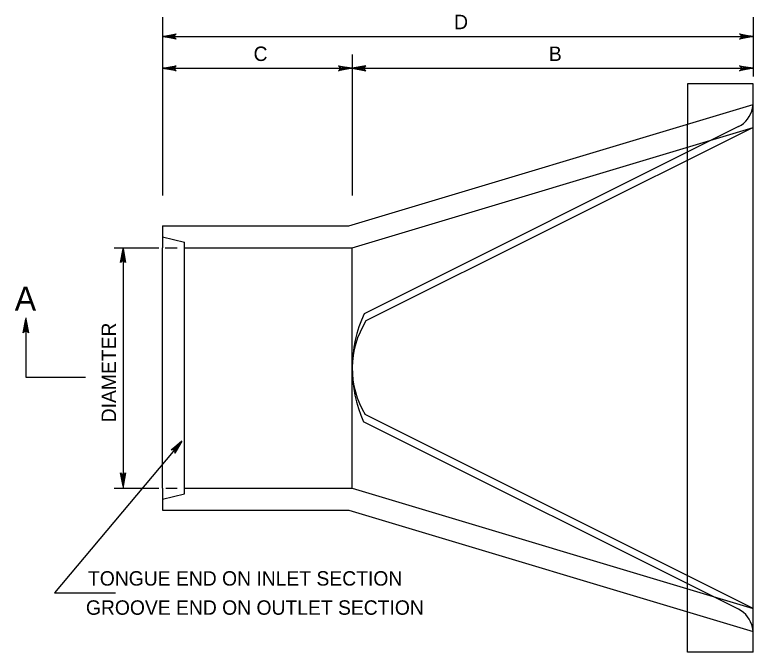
# Model space of a CAD drawing. Extents: x 1 to 8.2, y -2.1 to 8.1.
# Drawn here: x 0.968 to 4.037, y 5.467 to 8.117 of the extents above; entities that cross this region are included whole.
import ezdxf

# ---------------------------------------------------------------- set-up
doc = ezdxf.new("R2010")
doc.units = 0
for name, color, linetype in [('DETL-DIMS', 7, 'Continuous'), ('DETL-LINE', 7, 'Continuous'), ('DETL-NOTE', 7, 'Continuous'), ('DETL-TITL', 7, 'Continuous')]:
    doc.layers.add(name, color=color, linetype=linetype)

msp = doc.modelspace()

# ---------------------------------------------------------------- linework, layer by layer
at = {"layer": 'DETL-DIMS'}
for p, q in [((1.5824, 8.1071), (1.5824, 7.3661)), ((4.0369, 8.1071), (4.0369, 7.8601)), ((1.5824, 8.0267), (4.0369, 8.0267)), ((2.3702, 7.952), (2.3702, 7.3661)), ((1.5824, 7.8945), (2.3702, 7.8945)), ((2.3702, 7.8945), (4.0369, 7.8945)), ((1.3817, 7.1487), (1.5673, 7.1487)), ((1.4191, 7.1487), (1.4191, 6.1487)), ((1.5931, 7.1487), (1.6426, 7.1487)), ((1.0147, 6.6096), (1.0147, 6.8564)), ((1.2615, 6.6096), (1.0147, 6.6096)), ((1.6617, 6.345), (1.1335, 5.7132)), ((1.3817, 6.1487), (1.5673, 6.1487)), ((1.5953, 6.1487), (1.6426, 6.1487)), ((1.1335, 5.7132), (1.3871, 5.7132))]:
    msp.add_line(p, q, dxfattribs=at)
for points in [[(1.5824, 8.0267), (1.6388, 8.0372), (1.6345, 8.0342), (1.6323, 8.0304), (1.6316, 8.0267), (1.6323, 8.0229), (1.6345, 8.0191), (1.6388, 8.0161), (1.5824, 8.0267), (1.6345, 8.0191), (1.6323, 8.0229), (1.5824, 8.0267), (1.6316, 8.0267), (1.6323, 8.0304), (1.5824, 8.0267), (1.6345, 8.0342)], [(4.0369, 8.0267), (3.9804, 8.0161), (3.9848, 8.0191), (3.987, 8.0229), (3.9877, 8.0267), (3.987, 8.0304), (3.9848, 8.0342), (3.9804, 8.0372), (4.0369, 8.0267), (3.9848, 8.0342), (3.987, 8.0304), (4.0369, 8.0267), (3.9877, 8.0267), (3.987, 8.0229), (4.0369, 8.0267), (3.9848, 8.0191)], [(1.5824, 7.8945), (1.6388, 7.9051), (1.6345, 7.9021), (1.6323, 7.8983), (1.6316, 7.8945), (1.6323, 7.8908), (1.6345, 7.887), (1.6388, 7.8839), (1.5824, 7.8945), (1.6345, 7.887), (1.6323, 7.8908), (1.5824, 7.8945), (1.6316, 7.8945), (1.6323, 7.8983), (1.5824, 7.8945), (1.6345, 7.9021)], [(2.3702, 7.8945), (2.3138, 7.8839), (2.3181, 7.887), (2.3204, 7.8908), (2.321, 7.8945), (2.3204, 7.8983), (2.3181, 7.9021), (2.3138, 7.9051), (2.3702, 7.8945), (2.3181, 7.9021), (2.3204, 7.8983), (2.3702, 7.8945), (2.321, 7.8945), (2.3204, 7.8908), (2.3702, 7.8945), (2.3181, 7.887)], [(2.3702, 7.8945), (2.4267, 7.8839), (2.4224, 7.887), (2.4201, 7.8908), (2.4195, 7.8945), (2.4201, 7.8983), (2.4224, 7.9021), (2.4267, 7.9051), (2.3702, 7.8945), (2.4224, 7.9021), (2.4201, 7.8983), (2.3702, 7.8945), (2.4195, 7.8945), (2.4201, 7.8908), (2.3702, 7.8945), (2.4224, 7.887)], [(4.0369, 7.8945), (3.9804, 7.8839), (3.9848, 7.887), (3.987, 7.8908), (3.9877, 7.8945), (3.987, 7.8983), (3.9848, 7.9021), (3.9804, 7.9051), (4.0369, 7.8945), (3.9848, 7.9021), (3.987, 7.8983), (4.0369, 7.8945), (3.9877, 7.8945), (3.987, 7.8908), (4.0369, 7.8945), (3.9848, 7.887)], [(1.4182, 7.1433), (1.4288, 7.0868), (1.4258, 7.0912), (1.422, 7.0934), (1.4182, 7.0941), (1.4144, 7.0934), (1.4106, 7.0912), (1.4076, 7.0868), (1.4182, 7.1433), (1.4106, 7.0912), (1.4144, 7.0934), (1.4182, 7.1433), (1.4182, 7.0941), (1.422, 7.0934), (1.4182, 7.1433), (1.4258, 7.0912)], [(1.0138, 6.8511), (1.0244, 6.7946), (1.0214, 6.799), (1.0176, 6.8012), (1.0138, 6.8018), (1.01, 6.8012), (1.0062, 6.799), (1.0032, 6.7946), (1.0138, 6.8511), (1.0062, 6.799), (1.01, 6.8012), (1.0138, 6.8511), (1.0138, 6.8018), (1.0176, 6.8012), (1.0138, 6.8511), (1.0214, 6.799)], [(1.0138, 6.8511), (1.0244, 6.7946), (1.0214, 6.799), (1.0176, 6.8012), (1.0138, 6.8018), (1.01, 6.8012), (1.0062, 6.799), (1.0032, 6.7946), (1.0138, 6.8511), (1.0062, 6.799), (1.01, 6.8012), (1.0138, 6.8511), (1.0138, 6.8018), (1.0176, 6.8012), (1.0138, 6.8511), (1.0214, 6.799)], [(1.6617, 6.345), (1.6336, 6.2949), (1.634, 6.3002), (1.6326, 6.3043), (1.6301, 6.3073), (1.6268, 6.3092), (1.6224, 6.3099), (1.6173, 6.3085), (1.6617, 6.345), (1.6224, 6.3099), (1.6268, 6.3092), (1.6617, 6.345), (1.6301, 6.3073), (1.6326, 6.3043), (1.6617, 6.345), (1.634, 6.3002)], [(1.4182, 6.1567), (1.4076, 6.2132), (1.4106, 6.2088), (1.4144, 6.2066), (1.4182, 6.2059), (1.422, 6.2066), (1.4258, 6.2088), (1.4288, 6.2132), (1.4182, 6.1567), (1.4258, 6.2088), (1.422, 6.2066), (1.4182, 6.1567), (1.4182, 6.2059), (1.4144, 6.2066), (1.4182, 6.1567), (1.4106, 6.2088)]]:
    msp.add_lwpolyline(points, dxfattribs=at)
at = {"layer": 'DETL-LINE'}
for p, q in [((3.7642, 7.8305), (3.7642, 7.6617)), ((4.0369, 7.8305), (3.7642, 7.8305)), ((4.0369, 5.4669), (4.0369, 7.8305)), ((2.3569, 7.2396), (4.0369, 7.7436)), ((4.0338, 7.7281), (4.0369, 7.7436)), ((2.3702, 7.1487), (4.0369, 7.6487)), ((3.9756, 7.6519), (2.4198, 6.874)), ((4.0369, 7.6487), (2.4274, 6.8439)), ((3.7642, 5.6356), (3.7642, 7.6617)), ((1.5824, 7.2396), (2.3569, 7.2396)), ((1.5824, 7.2396), (1.5824, 7.1487)), ((1.5824, 7.1941), (1.6733, 7.1714)), ((1.6733, 6.1259), (1.6733, 7.1714)), ((1.5824, 6.1487), (1.5824, 7.1487)), ((1.6733, 7.1487), (2.3702, 7.1487)), ((2.3702, 6.1487), (2.3702, 7.1487)), ((4.0369, 5.6487), (2.4243, 6.4549)), ((3.9756, 5.6454), (2.4166, 6.4249)), ((1.5824, 6.1487), (1.5824, 6.0577)), ((1.6733, 6.1487), (2.3702, 6.1487)), ((2.3702, 6.1487), (4.0369, 5.6487)), ((1.5824, 6.1032), (1.6733, 6.1259)), ((1.5824, 6.0577), (2.3569, 6.0577)), ((2.3569, 6.0577), (4.0369, 5.5537)), ((3.7642, 5.4669), (3.7642, 5.6356)), ((4.0369, 5.5537), (4.0338, 5.5692)), ((4.0369, 5.4669), (3.7642, 5.4669))]:
    msp.add_line(p, q, dxfattribs=at)
for centre, radius, start, end in [((3.9268, 7.7495), 0.1091, 296.5651, 348.7042), ((2.9199, 6.6459), 0.5496, 155.487, 203.7065), ((2.7382, 6.647), 0.3679, 147.6422, 211.4636), ((3.9268, 5.5479), 0.1091, 11.2954, 63.4349)]:
    msp.add_arc(centre, radius, start, end, dxfattribs=at)

# ---------------------------------------------------------------- texts
at = {"layer": 'DETL-NOTE'}
for s, p in [('D', (2.7937, 8.057)), ('C', (1.9604, 7.9248)), ('B', (3.1876, 7.9248)), ('TONGUE END ON INLET SECTION', (1.2723, 5.7438)), ('GROOVE END ON OUTLET SECTION', (1.2637, 5.6226))]:
    msp.add_text(s, height=0.06, dxfattribs=at).set_placement(p)
msp.add_text('DIAMETER', height=0.06, rotation=90, dxfattribs=at).set_placement((1.3888, 6.4227))
at = {"layer": 'DETL-TITL'}
msp.add_text('A', height=0.1, dxfattribs=at).set_placement((0.9677, 6.8867))

doc.saveas('drawing.dxf')
